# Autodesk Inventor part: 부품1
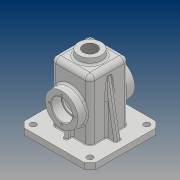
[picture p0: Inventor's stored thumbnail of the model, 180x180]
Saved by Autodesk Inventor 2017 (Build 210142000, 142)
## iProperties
Part Number: 부품1
Material: 일반
Document SubType Name: Modeling
Designer: 20
Density: 1 g/cm^3
Appearance: 기본값
Mass: 292.127 g
Surface Area: 897.877 cm^2
Volume: 292.127 cm^3
Author: 20
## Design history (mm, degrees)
sketch "스케치1"
  geometry: L1 (-32.5, 32.5)-(32.5, 32.5); L2 (32.5, 32.5)-(32.5, -32.5); L3 (32.5, -32.5)-(-32.5, -32.5); L4 (-32.5, -32.5)-(-32.5, 32.5); L5 (-32.5, 32.5)-(32.5, -32.5); L6 (32.5, 32.5)-(-32.5, -32.5); 1 further point
  constraints: 12 end point, 2 midpoint, 2 parallel, 1 horizontal, 1 perpendicular
  dimensions: "d0" = 65 distance of L2.end L3.end; "d1" = 65 distance of L1.end L2.end
extrude "돌출1" new body sketch "스케치1" distance "d2" = 100; taper "d3" = 0 deg
fillet "모깎기1" dims "d4" = 8
fillet "모깎기2" dims "d5" = 8
feature "쉘1" dims "d8" = 5
sketch "스케치3"
  geometry: L1 (-60, -60)-(60, -60); L2 (60, -60)-(60, 60); L3 (60, 60)-(-60, 60); L4 (-60, 60)-(-60, -60); L5 (-60, -60)-(60, 60); L6 (60, -60)-(-60, 60); L7 (-27.5, -24.5)-(-27.5, 24.5) reference; L8 (27.5, 24.5)-(27.5, -24.5) reference; L9 (-24.5, 27.5)-(24.5, 27.5) reference; L10 (24.5, -27.5)-(-24.5, -27.5) reference; A1 r 3 centre (24.5, -24.5) between (24.5, -27.5) and (27.5, -24.5) reference; A2 r 3 centre (24.5, 24.5) between (27.5, 24.5) and (24.5, 27.5) reference; A3 r 3 centre (-24.5, 24.5) between (-24.5, 27.5) and (-27.5, 24.5) reference; A4 r 3 centre (-24.5, -24.5) between (-27.5, -24.5) and (-24.5, -27.5) reference; 5 further points
  constraints: 12 end point, 2 midpoint, 2 parallel, 1 horizontal, 1 perpendicular
  dimensions: "d9" = 120 distance of L3.end L2.end; "d10" = 120 distance of L2.end L1.end
extrude "돌출2" join sketch "스케치3" distance "d11" = 10; taper "d12" = 0 deg
sketch "스케치4"
  geometry: C1 r 20 at (0, 0); 1 further point
  constraints: 1 centre point, 1 coincident
  dimensions: "d13" = 40 diameter of C1
extrude "돌출3" join sketch "스케치4" distance "d14" = 10; taper "d15" = -5 deg
hole "구멍1" diameter "d18" = 22.835; stored, may be unused: countersink angle "d22" = 90 deg, drill point angle "d24" = 0 deg; dims "d16" = 10, "d17" = 10, "d19" = 50, "d20" = 4, "d21" = 2, "d23" = 59.3
chamfer "모따기1" distance "d25" = 10; stored, may be unused: second distance "d26" = 2, angle "d27" = 45 deg
sketch "스케치5"
  geometry: L1 (74.5, -92)-(-25.5, -92) reference; L2 (74.5, -102)-(-25.5, -102) reference; C1 r 27.5 at (24.5, -47); 2 further points
  constraints: 1 centre point, 1 midpoint, 1 vertical alignment
  dimensions: "d28" = 55 diameter of C1; "d29" = 55 distance from line of L2 C1.centre
extrude "돌출4" join sketch "스케치5" distance "d30" = 15; taper "d31" = 0 deg
sketch "스케치6"
  geometry: C1 r 27.5 at (0, 0) reference; C2 r 17.5 at (0, 0); 1 further point
  constraints: 1 centre point, 1 coincident
  dimensions: "d32" = 35 diameter of C2
extrude "돌출5" cut sketch "스케치6" distance "d33" = 17; taper "d34" = 0 deg
sketch "스케치7"
  geometry: C1 r 17.5 at (0, 0) reference; C2 r 17.5 at (0, 0) reference; C3 r 15 at (0, 0); 1 further point
  constraints: 1 centre point, 1 coincident
  dimensions: "d35" = 30 diameter of C3
extrude "돌출6" cut sketch "스케치7" distance "d36" = 3; taper "d37" = 0 deg
sketch "스케치8"
  geometry: L1 (60, 50)-(60, -50) reference; L2 (50, -60)-(-50, -60) reference; C1 r 5 at (47.5, -47.5); 1 further point
  constraints: 1 centre point
  dimensions: "d38" = 10 diameter of C1; "d39" = 12.5 distance from line of L1 C1.centre; "d40" = 12.5 distance from line of L2 C1.centre
extrude "돌출7" cut sketch "스케치8" stored distance "d41" = 3; taper "d42" = 0 deg
sketch "스케치9"
  geometry: L1 (-50, 0)-(-60, 0) reference; L2 (-48, 0)-(-36.539, 65); L3 (-60, 0)-(-60, -10) reference; 1 further point
  constraints: 2 end point, 1 point on line
  dimensions: "d49" = 12 distance from line of L3 L2.start; "d50" = 10 deg angle of L3 L2; "d51" = 65 vertical distance of L2.start L2.end
feature "리브1" sketch "스케치9" dims "d52" = 1, "d53" = 10, "d54" = 0, "d55" = 0, "d56" = 1, "d57" = 1
sketch "스케치11"
  geometry: L1 (-3, -27.5)-(3, -27.5); L2 (3, -27.5)-(3, -42.5); L3 (3, -42.5)-(-3, -42.5); L4 (-3, -42.5)-(-3, -27.5); L5 (50, -60)-(-50, -60) reference; L6 (-24.5, -27.5)-(24.5, -27.5) reference; 3 further points
  constraints: 8 end point, 2 midpoint, 2 parallel, 1 horizontal, 1 perpendicular, 1 point on line, 1 vertical alignment
  dimensions: "d58" = 6 distance of L2.end L3.end; "d59" = 15 distance of L1.end L2.end
extrude "돌출8" join sketch "스케치11" stored distance "d60" = 3; taper "d61" = 0 deg
sketch "스케치12"
  geometry: L1 (50, -45)-(-50, -45) reference; C1 r 15 at (0, 0) reference; 3 further points
  constraints: 1 midpoint, 1 vertical alignment
  dimensions: "d62" = 21 distance of C1.centre point (0, 21)
hole "구멍2" sketch "스케치12" at (0, 21) diameter "d63" = 3.242; stored, may be unused: countersink angle "d67" = 90 deg, drill point angle "d69" = 118 deg; dims "d64" = 8, "d65" = 4, "d66" = 2, "d68" = 10
fillet "모깎기3" dims "d73" = 0.3
fillet "모깎기4" dims "d74" = 3
fillet "모깎기5" dims "d75" = 3
fillet "모깎기6" dims "d76" = 3
node "작업 평면2"
sketch "스케치13"
  geometry: L1 (43.625, -18)-(5.375, -18) reference; L2 (57, 0)-(57, 92) reference; 3 further points
  constraints: 1 other
  dimensions: "d82" = 26 distance from line of L1 point (24.5, 8); "d83" = 32.5 distance from line of L2 point (24.5, 8)
feature "엠보싱1" sketch "스케치13" dims "d9" = 120, "d10" = 120, "d84" = 0.5, "d85" = 0
chamfer "모따기2" distance "d89" = 1; stored, may be unused: second distance "d90" = 2, angle "d91" = 45 deg
fillet "모깎기15" dims "d93" = 3
fillet "모깎기16" dims "d94" = 3
fillet "모깎기17" dims "d95" = 3
fillet "모깎기18" dims "d96" = 1
node "솔리드1"
mirror "미러1"
pattern_linear "직사각형 패턴1" dims "d45" = 95, "d48" = 95
mirror "미러2"
mirror "미러3"
pattern_circular "원형 패턴1" dims angle "d71" = 360 deg
mirror "미러4"
node "작업 평면1"
other parameters: "d81" = 47
